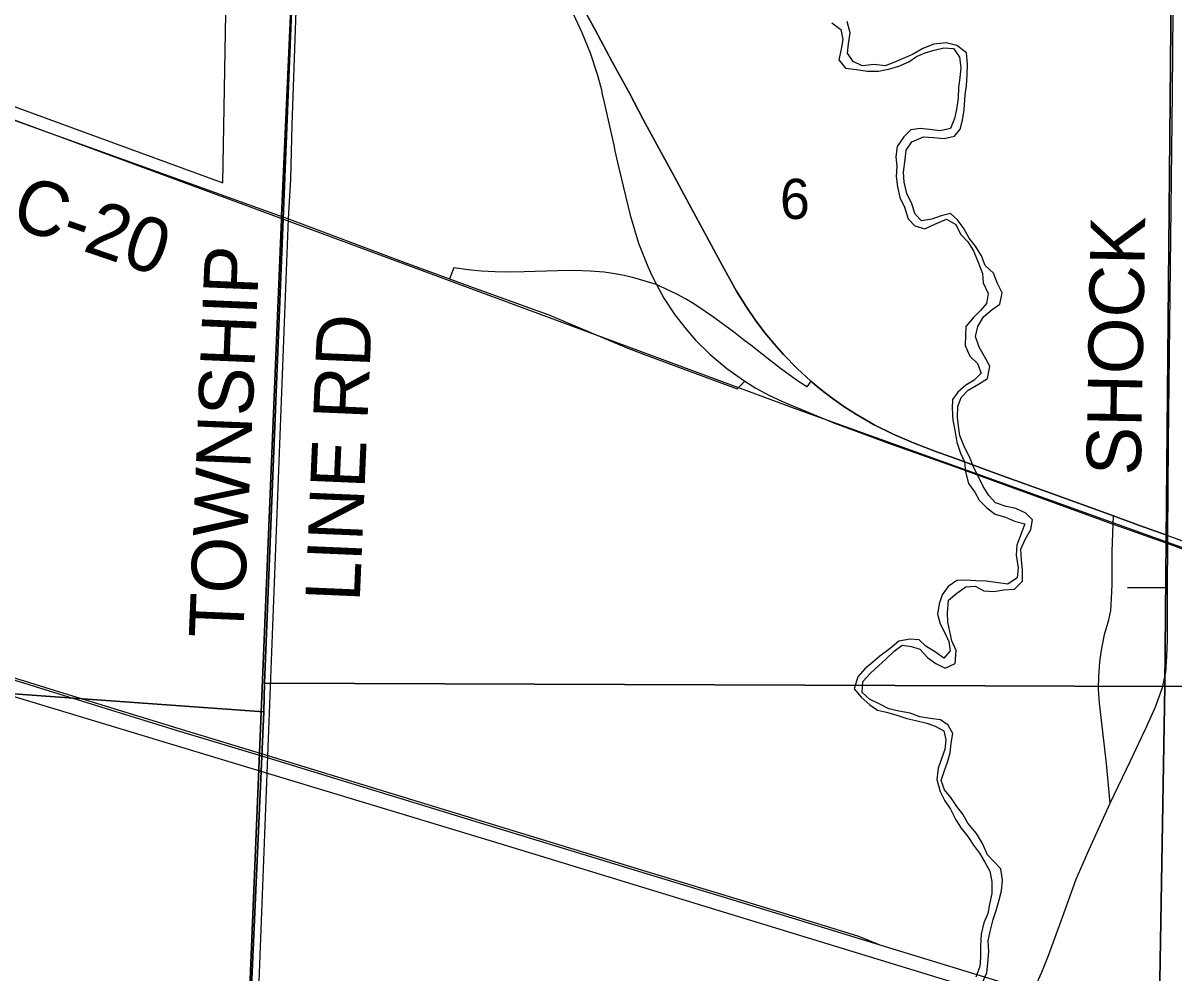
# Model space of a CAD drawing. Extents: x 36.7 to 70.7, y 0 to 22.
# Drawn here: x 41.074 to 42.275, y 18.615 to 19.606 of the extents above; entities that cross this region are included whole.
import ezdxf

# ---------------------------------------------------------------- set-up
doc = ezdxf.new("R2010")
doc.units = 0
for name, color, linetype in [('Default', 7, 'Continuous'), ('GM_X_County_Road', 7, 'Continuous'), ('GM_X_County_Road_Text', 7, 'Continuous'), ('GM_X_Interchange_Ramps', 7, 'Continuous'), ('GM_X_Minor_River', 7, 'Continuous'), ('GM_X_Rail_Line', 7, 'Continuous'), ('GM_X_Section', 7, 'Continuous'), ('GM_X_Section_Text', 7, 'Continuous'), ('GM_X_State_Route', 7, 'Continuous'), ('GM_X_Township_Road', 7, 'Continuous'), ('GM_X_Township_Road_Text', 7, 'Continuous'), ('GM_X_US_Route', 7, 'Continuous')]:
    doc.layers.add(name, color=color, linetype=linetype)

msp = doc.modelspace()

# ---------------------------------------------------------------- linework, layer by layer
at = {"layer": 'Default'}
msp.add_lwpolyline([(41.0256, 19.5334), (41.2829, 19.4397), (41.2894, 19.813), (41.297, 19.8129), (41.297, 20.0292), (41.36, 20.0281), (41.36, 20.0684), (41.2347, 20.3107)], dxfattribs=at)
at = {"layer": 'GM_X_County_Road'}
for p, q in [((41.3291, 18.8232), (41.3514, 19.402)), ((41.3138, 18.4272), (41.3291, 18.8232))]:
    msp.add_line(p, q, dxfattribs=at)
for points in [[(41.3514, 19.402), (41.3538, 19.4435), (41.3553, 19.5003), (41.3593, 19.6192), (41.3637, 19.743), (41.3661, 19.8126), (41.367, 19.8149)], [(40.8306, 19.5898), (41.005, 19.5265), (41.3443, 19.4045), (41.3514, 19.402)], [(41.3514, 19.402), (41.4699, 19.3575), (41.4727, 19.3565)], [(41.4727, 19.3565), (41.5195, 19.3393), (41.539, 19.3322)], [(41.539, 19.3322), (41.6229, 19.3018), (41.7038, 19.2677)]]:
    msp.add_lwpolyline(points, dxfattribs=at)
at = {"layer": 'GM_X_Interchange_Ramps'}
for points in [[(41.8352, 19.269), (41.8261, 19.2758), (41.8156, 19.2843), (41.7939, 19.3), (41.7862, 19.3055), (41.7743, 19.3134), (41.7656, 19.3186), (41.7564, 19.3236), (41.7388, 19.3319), (41.7353, 19.3334), (41.7116, 19.3406), (41.7016, 19.343), (41.6919, 19.3448), (41.6807, 19.3464), (41.6661, 19.3476), (41.6496, 19.3481), (41.6321, 19.3479), (41.5974, 19.3466), (41.5781, 19.3464), (41.5671, 19.3466), (41.5525, 19.3474), (41.5389, 19.3488), (41.524, 19.3509), (41.5195, 19.3393)], [(41.7038, 19.2677), (41.7219, 19.2607), (41.8196, 19.2245), (41.8275, 19.2327)], [(41.8965, 19.2328), (41.8921, 19.2267), (41.8815, 19.2338), (41.8648, 19.246), (41.8426, 19.2634), (41.8352, 19.269)]]:
    msp.add_lwpolyline(points, dxfattribs=at)
at = {"layer": 'GM_X_Minor_River'}
for points in [[(41.9184, 19.6065), (41.9277, 19.5998), (41.9297, 19.5891), (41.9279, 19.5792), (41.9257, 19.5679), (41.9327, 19.5594), (41.944, 19.5579), (41.9553, 19.5561), (41.9671, 19.5561), (41.9789, 19.5585), (41.9881, 19.5613), (41.9988, 19.5659), (42.0066, 19.5714), (42.0158, 19.5753), (42.025, 19.5781), (42.0353, 19.5805), (42.0451, 19.5798), (42.0517, 19.5709), (42.0529, 19.5599), (42.0519, 19.5493), (42.0505, 19.5394), (42.0501, 19.528), (42.0483, 19.5163), (42.0462, 19.5069), (42.0421, 19.4964), (42.0314, 19.494), (42.0204, 19.4954), (42.0106, 19.4965), (42.0007, 19.4949), (41.9933, 19.4878), (41.9866, 19.4774), (41.9852, 19.4668), (41.986, 19.4569), (41.9854, 19.4463), (41.987, 19.4356), (41.9893, 19.4242), (41.994, 19.4142), (41.9978, 19.4019), (42.0048, 19.3949), (42.0154, 19.3916), (42.0257, 19.3966), (42.038, 19.4016), (42.0477, 19.396), (42.0527, 19.386), (42.0601, 19.3782), (42.0663, 19.3685), (42.0706, 19.3574), (42.0755, 19.3451), (42.0764, 19.3352), (42.0814, 19.3241), (42.0796, 19.3138), (42.0733, 19.3064), (42.0659, 19.2987), (42.0581, 19.2898), (42.0578, 19.2803), (42.0576, 19.2697), (42.0622, 19.2589), (42.0703, 19.2511)], [(42.0874, 19.0133), (42.0977, 19.0149), (42.1091, 19.0157), (42.1173, 19.0239), (42.1172, 19.0353), (42.1164, 19.0463), (42.1155, 19.0573), (42.12, 19.0675), (42.1259, 19.0779), (42.1277, 19.0881), (42.1207, 19.0948), (42.1102, 19.0996), (42.1004, 19.1018), (42.0891, 19.1055), (42.0821, 19.1133), (42.0763, 19.1226), (42.0717, 19.1322), (42.0666, 19.1422), (42.062, 19.1537), (42.0566, 19.1637), (42.052, 19.176), (42.0504, 19.1856), (42.0495, 19.1951), (42.0498, 19.2061), (42.0531, 19.2155), (42.0605, 19.2233), (42.0713, 19.2294), (42.0809, 19.2356), (42.0832, 19.2484), (42.0777, 19.2585), (42.0719, 19.2681), (42.0681, 19.2792), (42.0706, 19.2898), (42.0766, 19.2999), (42.0855, 19.3076), (42.0936, 19.3131), (42.0962, 19.3248), (42.0912, 19.3344), (42.0869, 19.3452), (42.0784, 19.3534), (42.0745, 19.3634), (42.0683, 19.3734), (42.0617, 19.3819), (42.0559, 19.392), (42.0494, 19.4009), (42.042, 19.4075), (42.0324, 19.4051), (42.0225, 19.4016), (42.0118, 19.4), (42.0052, 19.407), (42.0017, 19.4177), (41.9966, 19.4285), (41.9939, 19.4404), (41.9931, 19.4506), (41.9949, 19.4639), (41.996, 19.4737), (42.0019, 19.4823), (42.0138, 19.4877), (42.0244, 19.487), (42.0354, 19.4859), (42.0464, 19.4883), (42.0523, 19.4957), (42.0548, 19.5051), (42.0563, 19.5157), (42.0574, 19.5313), (42.0588, 19.5411), (42.0595, 19.5521), (42.0598, 19.5635), (42.059, 19.5753), (42.0486, 19.5828), (42.0377, 19.5857), (42.0247, 19.5842), (42.0133, 19.5799), (42.0025, 19.5734), (41.9929, 19.5695), (41.9829, 19.5652), (41.9741, 19.5617), (41.9624, 19.5631), (41.9498, 19.5616), (41.9405, 19.5664), (41.9346, 19.5749), (41.9356, 19.5847), (41.9375, 19.5961), (41.9344, 19.6079)], [(42.0703, 19.2511), (42.0742, 19.2411), (42.0668, 19.2337), (42.058, 19.2286), (42.0498, 19.2213), (42.0443, 19.2134), (42.044, 19.204), (42.0445, 19.1918), (42.0465, 19.1815), (42.0488, 19.1689), (42.0526, 19.1574), (42.0566, 19.1486), (42.0578, 19.1379), (42.0609, 19.1257), (42.0675, 19.1167), (42.0722, 19.1083), (42.0799, 19.1005), (42.0888, 19.0938), (42.0994, 19.0908), (42.1091, 19.0864), (42.1196, 19.0838), (42.1156, 19.0725), (42.1115, 19.0616), (42.1108, 19.051), (42.1127, 19.0377), (42.1117, 19.0274), (42.102, 19.0209), (42.0896, 19.0227), (42.0793, 19.0238), (42.0687, 19.0244), (42.0581, 19.0251), (42.0486, 19.0246), (42.0398, 19.0184), (42.0335, 19.0098), (42.0302, 19.0001), (42.0287, 18.9895), (42.0315, 18.9795), (42.0358, 18.9707), (42.0405, 18.9611), (42.0417, 18.9511), (42.0351, 18.9434), (42.0265, 18.9497), (42.0165, 18.956), (42.0094, 18.9627), (42, 18.9633), (41.9882, 18.9614), (41.9792, 18.9536), (41.9684, 18.9456), (41.961, 18.9393), (41.9529, 18.9323), (41.9454, 18.9242), (41.9417, 18.9114), (41.949, 18.9028), (41.9579, 18.895), (41.9661, 18.8894), (41.9755, 18.8873), (41.9861, 18.884), (41.9966, 18.8806), (42.006, 18.8785), (42.0173, 18.8759), (42.0263, 18.8726), (42.0353, 18.8678), (42.0373, 18.8582), (42.0363, 18.8484), (42.033, 18.8394), (42.0293, 18.8289), (42.0279, 18.8171), (42.0313, 18.8045), (42.0364, 18.7945), (42.0422, 18.786), (42.0476, 18.7748), (42.0534, 18.7663), (42.0604, 18.7574), (42.0662, 18.7485), (42.0724, 18.74), (42.0779, 18.7307), (42.0833, 18.7214), (42.0853, 18.7104), (42.0853, 18.6978), (42.0827, 18.6869), (42.081, 18.6771), (42.0769, 18.6673), (42.0743, 18.6556), (42.0736, 18.6431), (42.0736, 18.6313), (42.0726, 18.6219), (42.0685, 18.6106)], [(42.0401, 19.004), (42.0487, 19.0113), (42.0583, 19.0179), (42.0678, 19.0188), (42.0768, 19.014), (42.0874, 19.0133)], [(42.0752, 18.6043), (42.08, 18.6152), (42.0811, 18.6254), (42.0822, 18.6376), (42.0813, 18.6486), (42.0835, 18.6584), (42.0865, 18.6709), (42.0902, 18.6814), (42.0931, 18.6912), (42.0952, 18.7006), (42.0963, 18.712), (42.0947, 18.7238), (42.0873, 18.7312), (42.0807, 18.7382), (42.0757, 18.7501), (42.0692, 18.7606), (42.0604, 18.7714), (42.0549, 18.7807), (42.0487, 18.7888), (42.0425, 18.7981), (42.0359, 18.8063), (42.0324, 18.8159), (42.0357, 18.8253), (42.039, 18.835), (42.0419, 18.8448), (42.0429, 18.8547), (42.0447, 18.8649), (42.0396, 18.8738), (42.0318, 18.8793), (42.0209, 18.8807), (42.0103, 18.8822), (42.0002, 18.8862), (41.9881, 18.8881), (41.9779, 18.8906), (41.9678, 18.8958), (41.9577, 18.9007), (41.9499, 18.9077), (41.9506, 18.9191), (41.9588, 18.928), (41.967, 18.9357), (41.9748, 18.9424), (41.9833, 18.9509), (41.9918, 18.9571), (42.0013, 18.9557), (42.0103, 18.9528), (42.0184, 18.9438), (42.027, 18.9379), (42.0367, 18.9331), (42.0471, 18.9381), (42.0482, 18.9514), (42.0435, 18.9617), (42.0415, 18.9713), (42.0395, 18.9812), (42.039, 18.9907), (42.0401, 19.004)]]:
    msp.add_lwpolyline(points, dxfattribs=at)
at = {"layer": 'GM_X_Rail_Line'}
for points in [[(39.9505, 19.9142), (40.2796, 19.7934), (40.742, 19.6245), (41.298, 19.4193), (41.8828, 19.2032), (42.4402, 19.0032), (43.0913, 18.7734), (43.6618, 18.5644), (44.5563, 18.22), (44.9526, 18.0665), (45.405, 17.9057), (45.5934, 17.8393)], [(39.4351, 19.5275), (39.5072, 19.4857), (39.6526, 19.4084), (39.8435, 19.3143), (39.9823, 19.2538), (40.1053, 19.2054), (40.2394, 19.1588), (40.707, 19.0117), (41.5752, 18.749), (42.4154, 18.492), (43.2547, 18.2349), (44.5058, 17.8517), (44.9515, 17.7199), (45.506, 17.5551), (45.5934, 17.5283)], [(40.4184, 19.1184), (40.5342, 19.0828), (40.5644, 19.0736), (40.633, 19.0526), (40.7242, 19.0248), (40.8662, 18.9816), (41.0703, 18.9191), (41.1118, 18.9063), (41.2352, 18.8682), (41.3301, 18.8394), (41.5595, 18.7692), (41.7245, 18.7187), (41.8299, 18.6867), (41.9106, 18.662), (41.99, 18.6377), (42.0947, 18.6058), (42.1775, 18.5805), (42.2523, 18.5576), (42.4612, 18.4939)], [(40.7086, 19.0296), (40.7249, 19.027), (40.8669, 18.9838), (41.071, 18.9213), (41.1125, 18.9085), (41.2359, 18.8705), (41.3307, 18.8416), (41.5602, 18.7714), (41.7252, 18.7209), (41.8306, 18.6889), (41.9112, 18.6642), (41.9461, 18.6535), (41.9703, 18.6437)]]:
    msp.add_lwpolyline(points, dxfattribs=at)
at = {"layer": 'GM_X_Section'}
for points in [[(40.2724, 19.8432), (40.3573, 19.8404), (41.3623, 19.8182), (41.3264, 18.9176), (41.3255, 18.8876), (40.2272, 18.9664)], [(43.2807, 19.8534), (43.2658, 18.9165), (42.2659, 18.914), (42.2743, 19.8312), (42.3088, 19.8313)], [(42.2743, 19.8312), (42.2659, 18.914), (41.3264, 18.9176), (41.3623, 19.8182)], [(41.3255, 18.8876), (41.2819, 17.9105), (41.2806, 17.8858), (40.1915, 17.9066), (40.2272, 18.9664)], [(42.2659, 18.914), (42.2487, 17.912), (41.2819, 17.9105), (41.3255, 18.8876), (41.3264, 18.9176)], [(43.2658, 18.9165), (43.2576, 17.9081), (42.2487, 17.912), (42.2659, 18.914)]]:
    msp.add_lwpolyline(points, close=True, dxfattribs=at)
at = {"layer": 'GM_X_State_Route'}
for points in [[(41.8965, 19.2328), (41.882, 19.2458), (41.868, 19.2605), (41.8581, 19.2715), (41.8489, 19.2827), (41.8391, 19.2955), (41.8289, 19.3104), (41.8189, 19.3267), (41.8042, 19.353), (41.7899, 19.3793), (41.7719, 19.4127), (41.754, 19.446), (41.7362, 19.4789), (41.7216, 19.5059), (41.707, 19.5331), (41.6892, 19.5659), (41.6713, 19.5992), (41.653, 19.633)], [(42.2124, 19.092), (42.1467, 19.1159), (42.0965, 19.134), (42.0472, 19.1519), (42.0259, 19.1597), (42.0044, 19.1679), (41.9822, 19.1775), (41.9625, 19.1872), (41.9439, 19.1979), (41.931, 19.2063), (41.9186, 19.215), (41.9069, 19.2239), (41.8965, 19.2328)], [(42.2689, 19.0716), (42.2385, 19.0825), (42.2124, 19.092)], [(42.1308, 18.6012), (42.1376, 18.616), (42.1445, 18.6334), (42.1589, 18.6732), (42.1734, 18.7129), (42.1853, 18.7408), (42.2086, 18.7924), (42.2299, 18.8363), (42.247, 18.8727), (42.2559, 18.8928), (42.2633, 18.9131), (42.2667, 18.9291), (42.2679, 18.9453), (42.2685, 18.9624), (42.2686, 19.0168), (42.2689, 19.0633)], [(42.2689, 19.0633), (42.2689, 19.0663), (42.2689, 19.0716)]]:
    msp.add_lwpolyline(points, dxfattribs=at)
at = {"layer": 'GM_X_Township_Road'}
msp.add_line((42.2686, 19.0168), (42.2267, 19.017), dxfattribs=at)
for points in [[(44.0245, 19.8612), (43.3189, 19.8494), (43.2806, 19.8481), (42.7713, 19.8373), (42.3685, 19.83), (42.3137, 19.8294), (42.2762, 19.8294), (41.5623, 19.8154), (41.5546, 19.8154), (41.5474, 19.8155), (41.5405, 19.8156), (41.3671, 19.8162), (41.3623, 19.8162), (41.3441, 19.4051), (41.344, 19.4017), (41.3037, 18.4227), (41.3025, 18.3936), (41.3022, 18.3874), (41.2661, 17.5372), (41.2499, 16.8815)], [(41.1522, 14.4699), (41.174, 14.9671), (41.1745, 14.977), (41.2392, 16.3776), (41.2409, 16.4152), (41.2499, 16.8815), (41.2661, 17.5372), (41.3022, 18.3874), (41.3025, 18.3936), (41.3037, 18.4227), (41.344, 19.4017), (41.3441, 19.4051), (41.3623, 19.8162), (40.8614, 19.8261), (40.8514, 19.8263), (40.7997, 19.8273), (40.7924, 19.8275), (40.7387, 19.8285), (40.7272, 19.8287), (40.1721, 19.8397)], [(42.2689, 19.0716), (42.2698, 19.1678), (42.2709, 19.2917), (42.2739, 19.534), (42.2764, 19.8288)], [(42.2086, 18.7924), (42.2048, 18.8335), (42.1978, 18.8967), (42.1966, 18.9113), (42.1969, 18.9245), (42.198, 18.9396), (42.1996, 18.9519), (42.2027, 18.9681), (42.2074, 18.9837), (42.2093, 18.9932), (42.2103, 19.0055), (42.2108, 19.0202), (42.2109, 19.055), (42.212, 19.0834), (42.2124, 19.092)]]:
    msp.add_lwpolyline(points, dxfattribs=at)
at = {"layer": 'GM_X_US_Route'}
for points in [[(41.6425, 19.6271), (41.6487, 19.6152), (41.6574, 19.5966), (41.6661, 19.5754), (41.6735, 19.5532), (41.6775, 19.5381), (41.6788, 19.5322)], [(41.653, 19.633), (41.6713, 19.5992), (41.6892, 19.5659), (41.707, 19.5331), (41.7216, 19.5059), (41.7362, 19.4789), (41.754, 19.446), (41.7719, 19.4127), (41.7899, 19.3793), (41.8042, 19.353), (41.8189, 19.3267), (41.8289, 19.3104), (41.8391, 19.2955), (41.8489, 19.2827), (41.8581, 19.2715), (41.868, 19.2605), (41.882, 19.2458), (41.8965, 19.2328)], [(41.6788, 19.5322), (41.6808, 19.5234), (41.6873, 19.4944), (41.6907, 19.4789), (41.692, 19.4729)], [(41.692, 19.4729), (41.6945, 19.4608), (41.7005, 19.436), (41.708, 19.406), (41.7166, 19.3767), (41.7262, 19.3522), (41.7303, 19.3428), (41.7353, 19.3334), (41.7429, 19.3193), (41.7544, 19.302), (41.7662, 19.2868), (41.7762, 19.2756), (41.7909, 19.2609), (41.8087, 19.2458), (41.8275, 19.2327)], [(41.8275, 19.2327), (41.8389, 19.2254), (41.8531, 19.2178), (41.8699, 19.2099), (41.8717, 19.2092)], [(41.8965, 19.2328), (41.9069, 19.2239), (41.9186, 19.215), (41.931, 19.2063), (41.9439, 19.1979), (41.9625, 19.1872), (41.9822, 19.1775), (42.0044, 19.1679), (42.0259, 19.1597), (42.0472, 19.1519), (42.0965, 19.134), (42.1467, 19.1159), (42.2124, 19.092)], [(41.8717, 19.2092), (41.9212, 19.1889), (41.9568, 19.1757), (41.9776, 19.1681), (42.0511, 19.1417)], [(42.0511, 19.1417), (42.0769, 19.1324), (42.212, 19.0834), (42.2689, 19.0633), (42.3145, 19.0466)], [(42.2124, 19.092), (42.2385, 19.0825), (42.2689, 19.0716)], [(42.2689, 19.0716), (42.2986, 19.0608), (42.3411, 19.0455), (42.4267, 19.0145), (42.4694, 18.999), (42.5157, 18.9826), (42.555, 18.9687), (42.6107, 18.9493), (42.6967, 18.9188), (42.7264, 18.9082), (42.7602, 18.8965)]]:
    msp.add_lwpolyline(points, dxfattribs=at)

# ---------------------------------------------------------------- texts
at = {"layer": 'GM_X_County_Road_Text'}
for s, rotation, p in [('C-20', 341.1304, (41.0594, 19.3951)), ('TOWNSHIP', 87.6083, (41.304, 18.9636)), ('LINE RD', 87.541, (41.4256, 19.0018))]:
    msp.add_text(s, height=0.05682, rotation=rotation, dxfattribs=at).set_placement(p)
at = {"layer": 'GM_X_Section_Text'}
msp.add_text('6', height=0.0419, rotation=0, dxfattribs=at).set_placement((41.8642, 19.4019))
at = {"layer": 'GM_X_Township_Road_Text'}
msp.add_text('SHOCK', height=0.05682, rotation=88.984, dxfattribs=at).set_placement((42.2406, 19.1339))

doc.saveas('drawing.dxf')
